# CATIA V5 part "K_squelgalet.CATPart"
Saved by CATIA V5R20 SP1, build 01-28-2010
Part number: squelgalet
Publications: "Rgaletaucontact", "dist_bâticerclecontactgalet", "Plan.1"
Bounding box of the stored display mesh (mm): x -10.41 to 0, y -9 to 9, z -9 to 9
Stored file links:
  G:\Khaled_CFAO_2011\SIL\SIL_GR2\zthiebault\Khaled\CAD_ThinkMOTION\K_squelgalet.CATPart
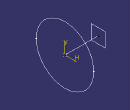
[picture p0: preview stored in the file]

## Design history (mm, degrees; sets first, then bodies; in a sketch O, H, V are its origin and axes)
Parameters
  Rgaletaucontact = 9 mm
  entraxegalets = 12 mm
  `dist_bâticerclecontactgalet` = 10.41 mm
Line1: type Normal, RefPoint Point1, RefSkin yz-plane, Start -10.41 {= -`dist_bâticerclecontactgalet`}, End 0
Set1 "setgéomflasque"
  Sketch1 on yz-plane, origin (0, 0, 0), H (0, 1, 0), V (0, 0, 1)
    circle A1 centre (0, 0) radius 9
    point P1 (0, 9)
    radius A1 = 9 {= Rgaletaucontact}
    coincidence: P1 A1, P1 V
  Point1: (0, 0, 0)
  Plane1: type Offset, RefPlane yz-plane, Offset -10.41 {= Line1.Start}
  Plane2: type OffsetPt, RefPlane Plane1, RefPoint Point1
Body1 (main body)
